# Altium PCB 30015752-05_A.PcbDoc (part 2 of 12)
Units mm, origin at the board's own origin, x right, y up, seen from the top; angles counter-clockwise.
Board outline 100.05 x 72 mm, 10 copper layers (Top, GND_2, Signal_3, Signal_4, PWR_5, GND_6, Signal_7, Signal_8, GND_9, Bottom), stack 1.493 mm thick; 577 components, 546 nets, 2389 pads, 1412 vias.
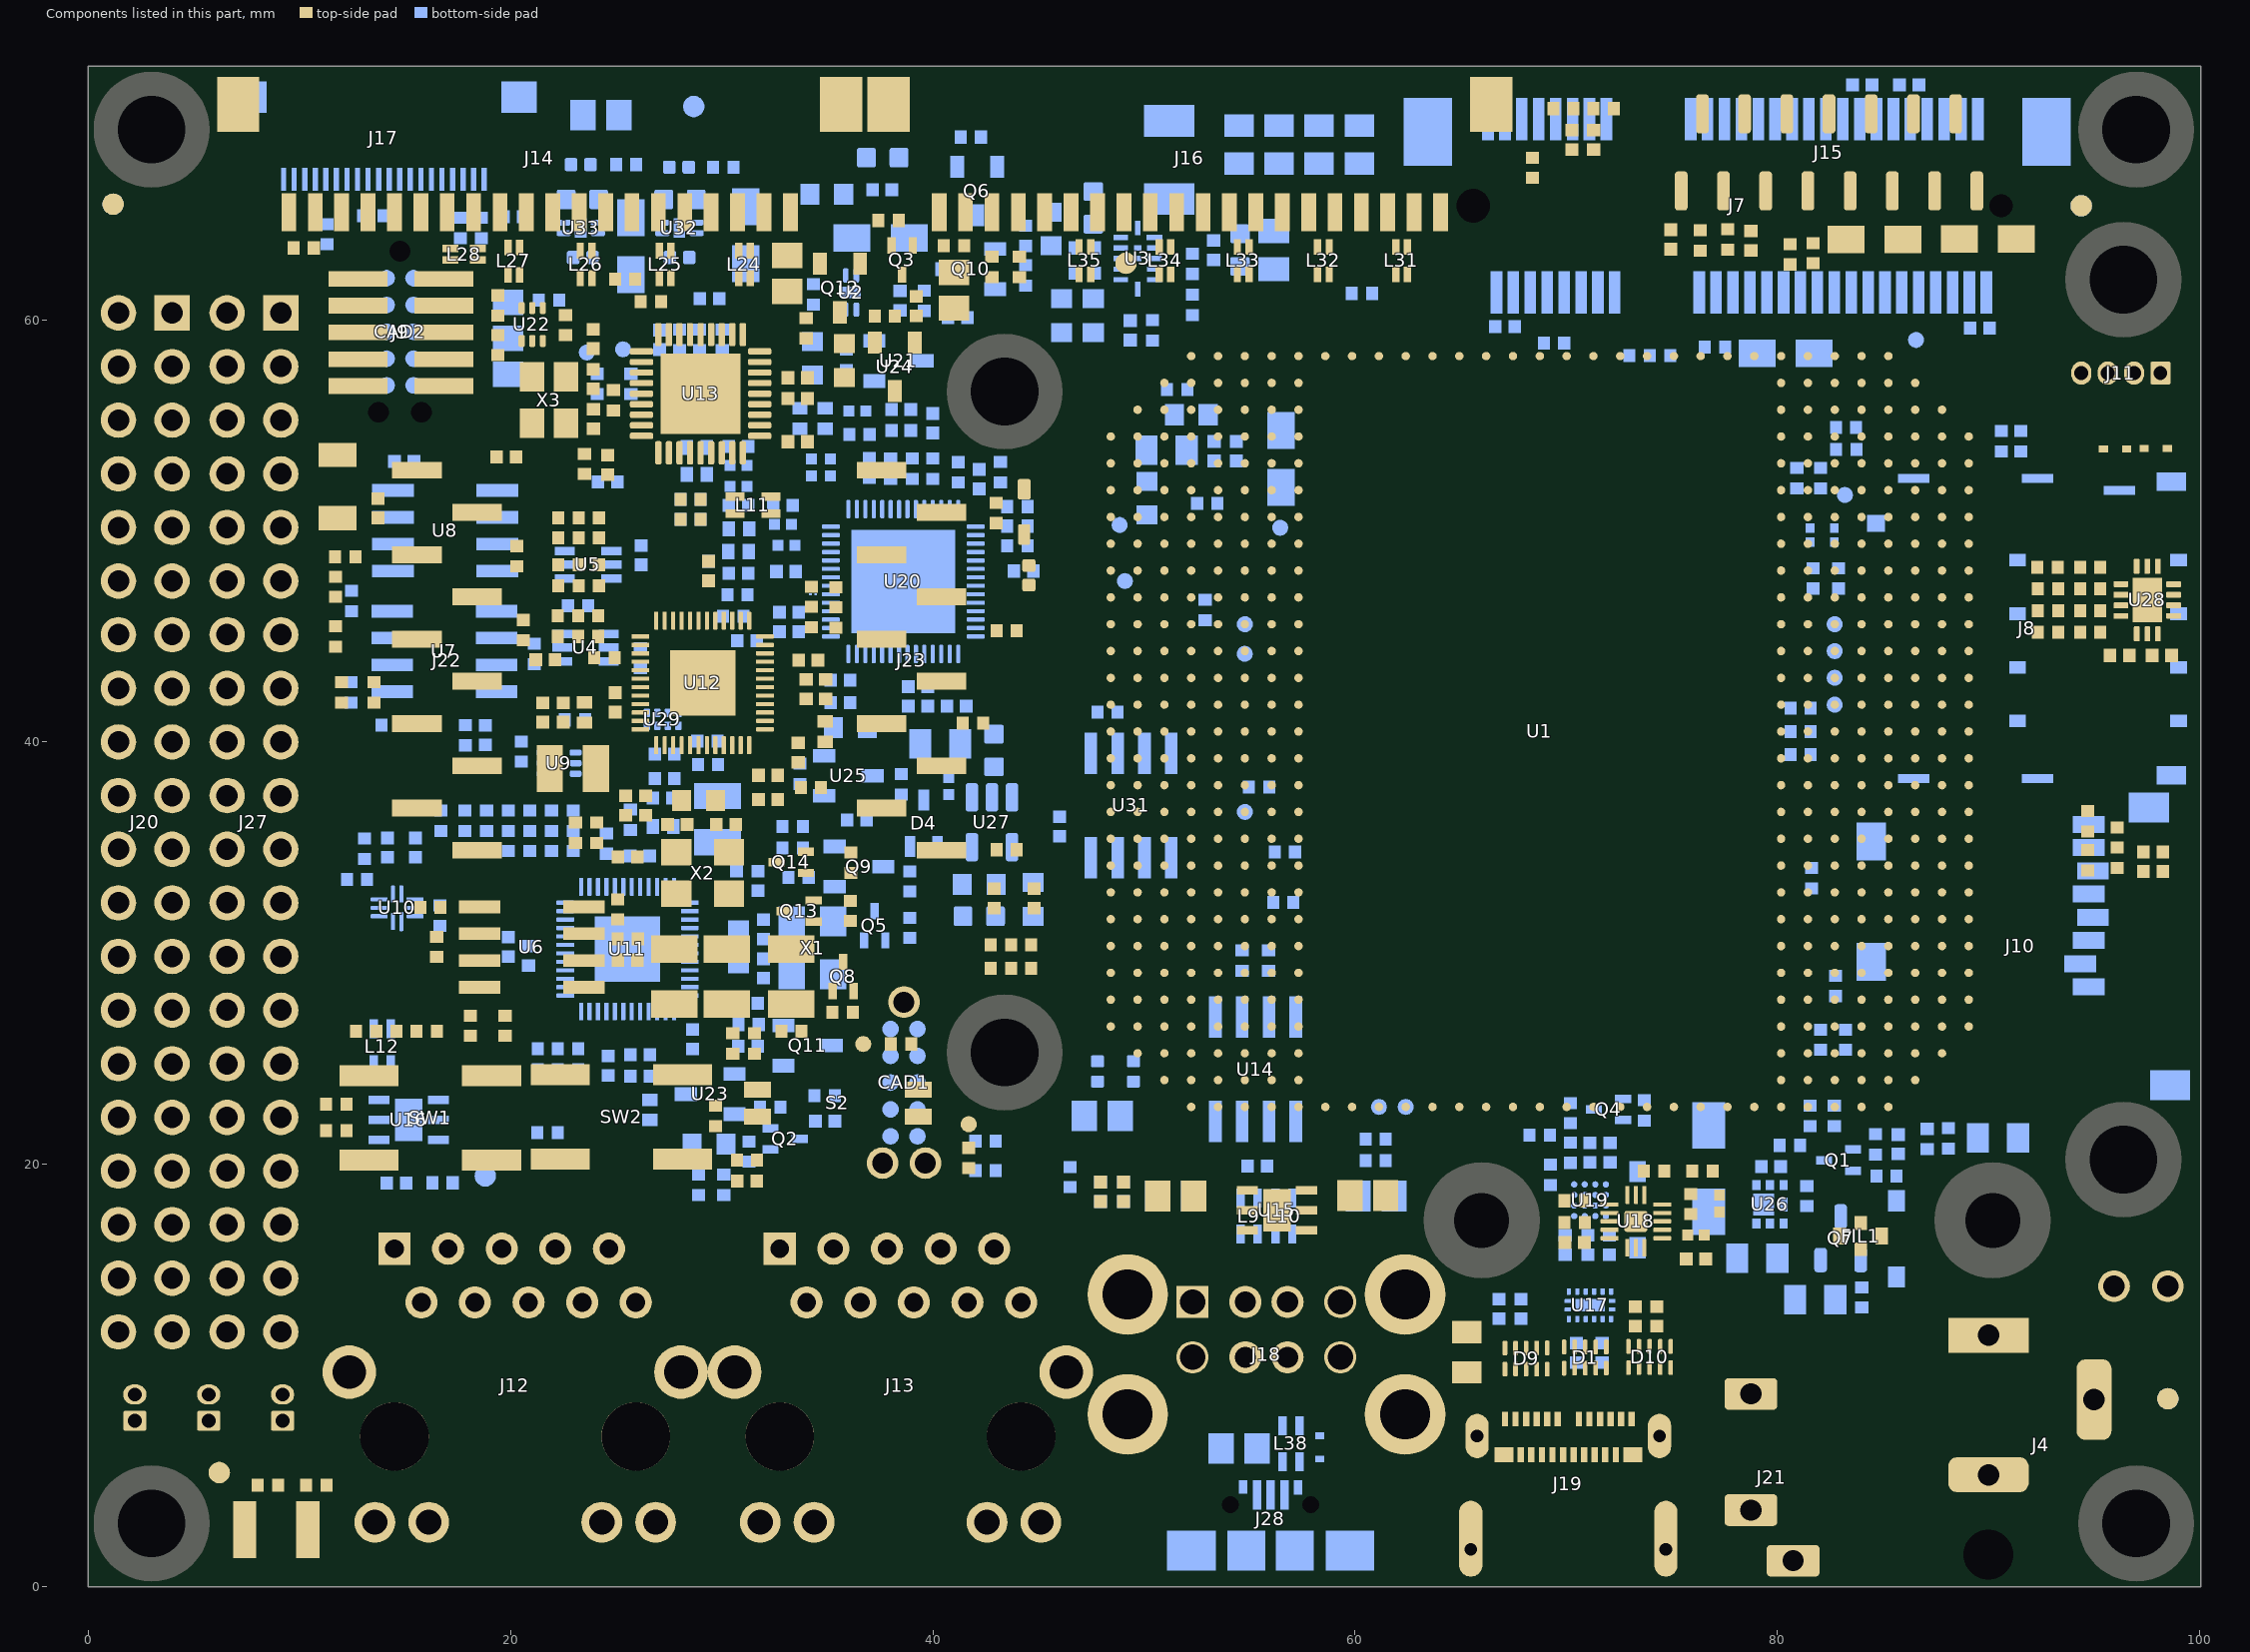
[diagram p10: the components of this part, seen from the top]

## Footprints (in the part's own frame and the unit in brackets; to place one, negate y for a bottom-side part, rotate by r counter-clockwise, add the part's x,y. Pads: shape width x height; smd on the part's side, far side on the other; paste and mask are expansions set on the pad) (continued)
CAPC0603X33N [mm]
  rect 0.46x0.42 smd: 1(-0.33,0) 2(0.33,0)
  body extent -0.3,-0.16 0.3,0.16, height 0.33
CAPC1005X55L [mm]
  rect 0.52x0.52 smd mask+0.05: 1(-0.4,0) 2(0.4,0)
  body extent -0.5,-0.25 0.5,0.25, height 0.55
CAPC1005X55N#1 [mm]
  rect 0.6x0.62 smd mask+0.05: 1(-0.46,0) 2(0.46,0)
  body extent -0.5,-0.25 0.5,0.25, height 0.55
CAPC1005X55N#2 [mm]
  rrect30% 0.6x0.62 smd mask+0.1: 1(-0.46,0) 2(0.46,0)
  body extent -0.5,-0.25 0.5,0.25, height 0.55
CAPC1608X90N [mm] "0603"
  rrect22% 0.89x0.93 smd: 1(-0.77,0) 2(0.77,0)
  body extent -0.8,-0.4 0.8,0.4, height 0.9
CAPC2013X135N [mm] "0805, 1.35mm max height"
  rect 1.05x1.4 smd: 1(-0.9,0) 2(0.9,0)
  body extent -1,-0.62 1,0.63, height 1.35
CAPC2013X145N [mm] "0805, 1.45mm max height"
  rect 1.15x1.45 smd: 1(-0.9,0) 2(0.9,0)
  body extent -1.05,-0.67 1.05,0.68, height 1.45
CAPC3216X190N [mm]
  rect 1.15x1.8 smd: 1(-1.5,0) 2(1.5,0)
  body extent -1.6,-0.8 1.6,0.8, height 1.9
CAPMP3216X120N [mm]
  rect 1.75x1.3 smd: 1(-1.35,0) 2(1.35,0)
  body extent -1.7,-0.9 1.7,0.9, height 1.21
CC8X_LGA [mm]
  round 0.4 smd mask+0.05: A4(-13.97,20.32) A5(-12.7,20.32) A6(-11.43,20.32) A7(-10.16,20.32) A8(-8.89,20.32) A9(-7.62,20.32) A10(-6.35,20.32) A11(-5.08,20.32) A12(-3.81,20.32) A13(-2.54,20.32) A14(-1.27,20.32) A15(0,20.32) A16(1.27,20.32) A17(2.54,20.32) A18(3.81,20.32) A19(5.08,20.32) A20(6.35,20.32) A21(7.62,20.32) A22(8.89,20.32) A23(10.16,20.32) A24(11.43,20.32) A25(12.7,20.32) A26(13.97,20.32) AA1(-17.78,-5.08) AA29(17.78,-5.08) AB1(-17.78,-6.35) AB29(17.78,-6.35) AC1(-17.78,-7.62) AC29(17.78,-7.62) AD1(-17.78,-8.89) AD29(17.78,-8.89) AE1(-17.78,-10.16) AE29(17.78,-10.16) AF1(-17.78,-11.43) AF2(-16.51,-11.43) AF3(-15.24,-11.43) AF4(-13.97,-11.43) AF5(-12.7,-11.43) AF6(-11.43,-11.43) AF7(-10.16,-11.43) AF8(-8.89,-11.43) AF9(-7.62,-11.43) AF10(-6.35,-11.43) AF11(-5.08,-11.43) AF12(-3.81,-11.43) AF13(-2.54,-11.43) AF14(-1.27,-11.43) AF15(0,-11.43) AF16(1.27,-11.43) AF17(2.54,-11.43) AF18(3.81,-11.43) AF19(5.08,-11.43) AF20(6.35,-11.43) AF21(7.62,-11.43) AF22(8.89,-11.43) AF23(10.16,-11.43) AF24(11.43,-11.43) AF25(12.7,-11.43) AF26(13.97,-11.43) AF27(15.24,-11.43) AF28(16.51,-11.43) AF29(17.78,-11.43) AG1(-17.78,-12.7) AG2(-16.51,-12.7) AG3(-15.24,-12.7) AG4(-13.97,-12.7) AG5(-12.7,-12.7) AG6(-11.43,-12.7) AG7(-10.16,-12.7) AG8(-8.89,-12.7) AG9(-7.62,-12.7) AG10(-6.35,-12.7) AG11(-5.08,-12.7) AG12(-3.81,-12.7) AG13(-2.54,-12.7) AG14(-1.27,-12.7) AG15(0,-12.7) AG16(1.27,-12.7) AG17(2.54,-12.7) AG18(3.81,-12.7) AG19(5.08,-12.7) AG20(6.35,-12.7) AG21(7.62,-12.7) AG22(8.89,-12.7) AG23(10.16,-12.7) AG24(11.43,-12.7) AG25(12.7,-12.7) AG26(13.97,-12.7) AG27(15.24,-12.7) AG28(16.51,-12.7) AG29(17.78,-12.7) AH1(-17.78,-13.97) AH2(-16.51,-13.97) AH3(-15.24,-13.97) AH4(-13.97,-13.97) AH5(-12.7,-13.97) AH6(-11.43,-13.97) AH7(-10.16,-13.97) AH8(-8.89,-13.97) AH9(-7.62,-13.97) AH10(-6.35,-13.97) AH11(-5.08,-13.97) AH12(-3.81,-13.97) AH13(-2.54,-13.97) AH14(-1.27,-13.97) AH15(0,-13.97) AH16(1.27,-13.97) AH17(2.54,-13.97) AH18(3.81,-13.97) AH19(5.08,-13.97) AH20(6.35,-13.97) AH21(7.62,-13.97) AH22(8.89,-13.97) AH23(10.16,-13.97) AH24(11.43,-13.97) AH25(12.7,-13.97) AH26(13.97,-13.97) AH27(15.24,-13.97) AH28(16.51,-13.97) AH29(17.78,-13.97) AJ1(-17.78,-15.24) AJ2(-16.51,-15.24) AJ3(-15.24,-15.24) AJ4(-13.97,-15.24) AJ5(-12.7,-15.24) AJ6(-11.43,-15.24) AJ7(-10.16,-15.24) AJ8(-8.89,-15.24) AJ9(-7.62,-15.24) AJ10(-6.35,-15.24) AJ11(-5.08,-15.24) AJ12(-3.81,-15.24) AJ13(-2.54,-15.24) AJ14(-1.27,-15.24) AJ15(0,-15.24) AJ16(1.27,-15.24) AJ17(2.54,-15.24) AJ18(3.81,-15.24) AJ19(5.08,-15.24) AJ20(6.35,-15.24) AJ21(7.62,-15.24) AJ22(8.89,-15.24) AJ23(10.16,-15.24) AJ24(11.43,-15.24) AJ25(12.7,-15.24) AJ26(13.97,-15.24) AJ27(15.24,-15.24) AJ28(16.51,-15.24) AJ29(17.78,-15.24) AK1(-17.78,-16.51) AK2(-16.51,-16.51) AK3(-15.24,-16.51) AK4(-13.97,-16.51) AK5(-12.7,-16.51) AK6(-11.43,-16.51) AK7(-10.16,-16.51) AK8(-8.89,-16.51) AK9(-7.62,-16.51) AK10(-6.35,-16.51) AK11(-5.08,-16.51) AK12(-3.81,-16.51) AK13(-2.54,-16.51) AK14(-1.27,-16.51) AK15(0,-16.51) AK16(1.27,-16.51) AK17(2.54,-16.51) AK18(3.81,-16.51) AK19(5.08,-16.51) AK20(6.35,-16.51) AK21(7.62,-16.51) AK22(8.89,-16.51) AK23(10.16,-16.51) AK24(11.43,-16.51) AK25(12.7,-16.51) AK26(13.97,-16.51) AK27(15.24,-16.51) AK28(16.51,-16.51) AK29(17.78,-16.51) AL2(-16.51,-17.78) AL3(-15.24,-17.78) AL4(-13.97,-17.78) AL5(-12.7,-17.78) AL6(-11.43,-17.78) AL7(-10.16,-17.78) AL8(-8.89,-17.78) AL9(-7.62,-17.78) AL10(-6.35,-17.78) AL11(-5.08,-17.78) AL12(-3.81,-17.78) AL13(-2.54,-17.78) AL14(-1.27,-17.78) AL15(0,-17.78) AL16(1.27,-17.78) AL17(2.54,-17.78) AL18(3.81,-17.78) AL19(5.08,-17.78) AL20(6.35,-17.78) AL21(7.62,-17.78) AL22(8.89,-17.78) AL23(10.16,-17.78) AL24(11.43,-17.78) AL25(12.7,-17.78) AL26(13.97,-17.78) AL27(15.24,-17.78) AL28(16.51,-17.78) AM3(-15.24,-19.05) AM4(-13.97,-19.05) AM5(-12.7,-19.05) AM6(-11.43,-19.05) AM7(-10.16,-19.05) AM8(-8.89,-19.05) AM9(-7.62,-19.05) AM10(-6.35,-19.05) AM11(-5.08,-19.05) AM12(-3.81,-19.05) AM13(-2.54,-19.05) AM14(-1.27,-19.05) AM15(0,-19.05) AM16(1.27,-19.05) AM17(2.54,-19.05) AM18(3.81,-19.05) AM19(5.08,-19.05) AM20(6.35,-19.05) AM21(7.62,-19.05) AM22(8.89,-19.05) AM23(10.16,-19.05) AM24(11.43,-19.05) AM25(12.7,-19.05) AM26(13.97,-19.05) AM27(15.24,-19.05) AN4(-13.97,-20.32) AN5(-12.7,-20.32) AN6(-11.43,-20.32) AN7(-10.16,-20.32) AN8(-8.89,-20.32) AN9(-7.62,-20.32) AN10(-6.35,-20.32) AN11(-5.08,-20.32) AN12(-3.81,-20.32) AN13(-2.54,-20.32) AN14(-1.27,-20.32) AN15(0,-20.32) AN16(1.27,-20.32) AN17(2.54,-20.32) AN18(3.81,-20.32) AN19(5.08,-20.32) AN20(6.35,-20.32) AN21(7.62,-20.32) AN22(8.89,-20.32) AN23(10.16,-20.32) AN24(11.43,-20.32) AN25(12.7,-20.32) AN26(13.97,-20.32) B3(-15.24,19.05) B4(-13.97,19.05) B5(-12.7,19.05) B6(-11.43,19.05) B7(-10.16,19.05) B8(-8.89,19.05) B9(-7.62,19.05) B10(-6.35,19.05) B11(-5.08,19.05) B12(-3.81,19.05) B13(-2.54,19.05) B14(-1.27,19.05) B15(0,19.05) B16(1.27,19.05) B17(2.54,19.05) B18(3.81,19.05) B19(5.08,19.05) B20(6.35,19.05) B21(7.62,19.05) B22(8.89,19.05) B23(10.16,19.05) B24(11.43,19.05) B25(12.7,19.05) B26(13.97,19.05) B27(15.24,19.05) C2(-16.51,17.78) C3(-15.24,17.78) C4(-13.97,17.78) C5(-12.7,17.78) C6(-11.43,17.78) C7(-10.16,17.78) C8(-8.89,17.78) C9(-7.62,17.78) C10(-6.35,17.78) C11(-5.08,17.78) C12(-3.81,17.78) C13(-2.54,17.78) C14(-1.27,17.78) C15(0,17.78) C16(1.27,17.78) C17(2.54,17.78) C18(3.81,17.78) C19(5.08,17.78) C20(6.35,17.78) C21(7.62,17.78) C22(8.89,17.78) C23(10.16,17.78) C24(11.43,17.78) C25(12.7,17.78) C26(13.97,17.78) C27(15.24,17.78) C28(16.51,17.78) D1(-17.78,16.51) D2(-16.51,16.51) D3(-15.24,16.51) D4(-13.97,16.51) D5(-12.7,16.51) D6(-11.43,16.51) D7(-10.16,16.51) D8(-8.89,16.51) D9(-7.62,16.51) D10(-6.35,16.51) D11(-5.08,16.51) D12(-3.81,16.51) D13(-2.54,16.51) D14(-1.27,16.51) D15(0,16.51) D16(1.27,16.51) D17(2.54,16.51) D18(3.81,16.51) D19(5.08,16.51) D20(6.35,16.51) D21(7.62,16.51) D22(8.89,16.51) D23(10.16,16.51) D24(11.43,16.51) D25(12.7,16.51) D26(13.97,16.51) D27(15.24,16.51) D28(16.51,16.51) D29(17.78,16.51) E1(-17.78,15.24) E2(-16.51,15.24) E3(-15.24,15.24) E4(-13.97,15.24) E5(-12.7,15.24) E6(-11.43,15.24) E7(-10.16,15.24) E8(-8.89,15.24) E9(-7.62,15.24) E10(-6.35,15.24) E11(-5.08,15.24) E12(-3.81,15.24) E13(-2.54,15.24) E14(-1.27,15.24) E15(0,15.24) E16(1.27,15.24) E17(2.54,15.24) E18(3.81,15.24) E19(5.08,15.24) E20(6.35,15.24) E21(7.62,15.24) E22(8.89,15.24) E23(10.16,15.24) E24(11.43,15.24) E25(12.7,15.24) E26(13.97,15.24) E27(15.24,15.24) E28(16.51,15.24) E29(17.78,15.24) F1(-17.78,13.97) F2(-16.51,13.97) F3(-15.24,13.97) F4(-13.97,13.97) F5(-12.7,13.97) F6(-11.43,13.97) F7(-10.16,13.97) F8(-8.89,13.97) F9(-7.62,13.97) F10(-6.35,13.97) F11(-5.08,13.97) F12(-3.81,13.97) F13(-2.54,13.97) F14(-1.27,13.97) F15(0,13.97) F16(1.27,13.97) F17(2.54,13.97) F18(3.81,13.97) F19(5.08,13.97) F20(6.35,13.97) F21(7.62,13.97) F22(8.89,13.97) F23(10.16,13.97) F24(11.43,13.97) F25(12.7,13.97) F26(13.97,13.97) F27(15.24,13.97) F28(16.51,13.97) F29(17.78,13.97) G1(-17.78,12.7) G2(-16.51,12.7) G3(-15.24,12.7) G4(-13.97,12.7) G5(-12.7,12.7) G6(-11.43,12.7) G7(-10.16,12.7) G8(-8.89,12.7) G9(-7.62,12.7) G10(-6.35,12.7) G11(-5.08,12.7) G12(-3.81,12.7) G13(-2.54,12.7) G14(-1.27,12.7) G15(0,12.7) G16(1.27,12.7) G17(2.54,12.7) G18(3.81,12.7) G19(5.08,12.7) G20(6.35,12.7) G21(7.62,12.7) G22(8.89,12.7) G23(10.16,12.7) G24(11.43,12.7) G25(12.7,12.7) G26(13.97,12.7) G27(15.24,12.7) G28(16.51,12.7) G29(17.78,12.7) H1(-17.78,11.43) H2(-16.51,11.43) H3(-15.24,11.43) H4(-13.97,11.43) H5(-12.7,11.43) H6(-11.43,11.43) H7(-10.16,11.43) H8(-8.89,11.43) H9(-7.62,11.43) H10(-6.35,11.43) H11(-5.08,11.43) H12(-3.81,11.43) H13(-2.54,11.43) H14(-1.27,11.43) H15(0,11.43) H16(1.27,11.43) H17(2.54,11.43) H18(3.81,11.43) H19(5.08,11.43) H20(6.35,11.43) H21(7.62,11.43) H22(8.89,11.43) H23(10.16,11.43) H24(11.43,11.43) H25(12.7,11.43) H26(13.97,11.43) H27(15.24,11.43) H28(16.51,11.43) H29(17.78,11.43) J1(-17.78,10.16) J29(17.78,10.16) K1(-17.78,8.89) K29(17.78,8.89) L1(-17.78,7.62) L29(17.78,7.62) M1(-17.78,6.35) M29(17.78,6.35) N1(-17.78,5.08) N29(17.78,5.08) P1(-17.78,3.81) P29(17.78,3.81) R1(-17.78,2.54) R29(17.78,2.54) T1(-17.78,1.27) T29(17.78,1.27) U1(-17.78,0) U29(17.78,0) V1(-17.78,-1.27) V29(17.78,-1.27) W1(-17.78,-2.54) W29(17.78,-2.54) Y1(-17.78,-3.81) Y29(17.78,-3.81)
  Keep-Out Layer board cut-out: 16.78,9.93 16.78,10.029 16.704,10.213 16.563,10.354 16.379,10.43 16.28,10.43 16.28,10.43 -16.28,10.43 -16.379,10.43 -16.563,10.354 -16.704,10.213 -16.78,10.029 -16.78,9.93 -16.78,9.93 -16.78,-9.93 -16.78,-10.029 -16.704,-10.213 -16.563,-10.354 -16.379,-10.43 -16.28,-10.43 -16.28,-10.43 16.28,-10.43 16.379,-10.43 16.563,-10.354 16.704,-10.213 16.78,-10.029 16.78,-9.93 16.78,-9.93
  body extent -20,-22.5 20,22.5, height 5.35
conn_CSCD443CCS011B00G [mil] "Bobbintron : CSCD443CCS011B00G"
  rect 65x150 hole 40 slot 126 at 90 deg: 1(0,0)
  rrect50% 65x150 / inner rect 65x150 / far side rrect50% 65x150 hole 40 slot 126 at 90 deg: 2(-260,0)
  rrect50% 150x65 / inner rect 150x65 / far side rrect50% 150x65 hole 40 slot 126 at 0 deg: 3(-120,-197.01)
  round 0 hole 93 unplated: 4(-409,0)
  body extent -571,-207 20,177, height 433
CUI_SJ1-3533N [mm] "CON PWR JCK STEREO 3.5MM R/A 3.05mm"
  rrect25% 1.5x2.5 hole 1 slot 2 at 90 deg: 1(0,0) 2(2.4,2) 3(7.9,2)
  body extent -5.2,-4 12.8,4.2, height 12.3
DIOM5127X229AN [mm]
  rect 2.2x1.55 smd: A(2.05,0) K(-2.05,0)
  silkscreen extent -3.45,1.33 -3.15,1.63, body extent -2.64,-1.4 2.64,1.4, height 2.34
FAIRCHILD_MICROFET_2X2 [mm]
  rect 0.47x0.4 smd mask+0.05: 1(-0.91,0.65) 2(-0.91,0) 3(-0.91,-0.65) 4(0.91,-0.65) 5(0.91,0) 6(0.91,0.65)
  rect 1.05x1 smd mask+0: 7(0,0.3)
  rect 0.66x0.4 smd mask+0.05: 8(0,-0.65)
  body extent -1,-1 1,1, height 0.85
FCI_SFW15S-2STE1LF [mm] "CONN FFC FPC VERT 15POS 1MM SMD"
  rrect50% 0.6x1.85 smd: 1(-7,-1.825) 2(-6,1.825) 3(-5,-1.825) 4(-4,1.825) 5(-3,-1.825) 6(-2,1.825) 7(-1,-1.825) 8(0,1.825) 9(1,-1.825) 10(2,1.825) 11(3,-1.825) 12(4,1.825) 13(5,-1.825) 14(6,1.825) 15(7,-1.825)
  body extent -10.7,-2.25 10.7,2.25, height 5.31
fiducial_40mil_round [mil]
  round 40 smd paste-40 mask+20: 1(0,0)
  Top pour cut-out: -40,0 -36.96,15.31 -28.28,28.28 -15.31,36.96 0,40 0,40 15.31,36.96 28.28,28.28 36.96,15.31 40,0 40,0 36.96,-15.31 28.28,-28.28 15.31,-36.96 0,-40 0,-40 -15.31,-36.96 -28.28,-28.28 -36.96,-15.31 -40,0
FIL_DLP11S [mm]
  rect 0.75x0.35 smd: 1(-0.65,-0.275) 2(0.65,-0.275) 3(0.65,0.275) 4(-0.65,0.275)
  body extent -0.67,-0.55 0.68,0.55, height 0.92
FIL_DLW21H [mm]
  rect 0.9x0.4 smd: 1(-0.85,-0.4) 2(0.85,-0.4) 3(0.85,0.4) 4(-0.85,0.4)
  body extent -1.1,-0.7 1.1,0.7, height 1
FIL_NFM21P [mm]
  rect 0.6x0.8 smd: 1(-1,0) 3(1,0)
  rect 0.6x0.65 smd: 2(0,0.625) 2(0,-0.625)
  silkscreen extent -2.05,-0.8 1.15,0.8, body extent -1,-0.62 1,0.63, height 0.85
FOXCONN_AS0B221-S68Q-7H [mm]
  rect 0.55x2 smd: 1(0.7,-4.1) 2(1.1,4.1) 3(1.5,-4.1) 4(1.9,4.1) 5(2.3,-4.1) 6(2.7,4.1) 7(3.1,-4.1) 8(3.5,4.1) 9(3.9,-4.1) 10(4.3,4.1) 11(4.7,-4.1) 12(5.1,4.1) 13(5.5,-4.1) 14(5.9,4.1) 15(6.3,-4.1) 16(6.7,4.1) 17(10.3,-4.1) 18(10.7,4.1) 19(11.1,-4.1) 20(11.5,4.1) 21(11.9,-4.1) 22(12.3,4.1) 23(12.7,-4.1) 24(13.1,4.1) 25(13.5,-4.1) 26(13.9,4.1) 27(14.3,-4.1) 28(14.7,4.1) 29(15.1,-4.1) 30(15.5,4.1) 31(15.9,-4.1) 32(16.3,4.1) 33(16.7,-4.1) 34(17.1,4.1) 35(17.5,-4.1) 36(17.9,4.1) 37(18.3,-4.1) 38(18.7,4.1) 39(19.1,-4.1) 40(19.5,4.1) 41(19.9,-4.1) 42(20.3,4.1) 43(20.7,-4.1) 44(21.1,4.1) 45(21.5,-4.1) 46(21.9,4.1) 47(22.3,-4.1) 48(22.7,4.1) 49(23.1,-4.1) 50(23.5,4.1) 51(23.9,-4.1) 52(24.3,4.1)
  round 0 hole 1.6 unplated: H1(0,0)
  round 0 hole 1.1 unplated: H2(25,0)
  rect 2.3x3.2 smd: MT1(-2.15,-3.5) MT2(27.15,-3.5)
  body extent -2.4,-4.75 27.4,4.75, height 6.8
HIROSE_DF14A-20P-1.25H [mm]
  rect 0.7x1.8 smd: 1(11.875,-2.55) 2(10.625,-2.55) 3(9.375,-2.55) 4(8.125,-2.55) 5(6.875,-2.55) 6(5.625,-2.55) 7(4.375,-2.55) 8(3.125,-2.55) 9(1.875,-2.55) 10(0.625,-2.55) 11(-0.625,-2.55) 12(-1.875,-2.55) 13(-3.125,-2.55) 14(-4.375,-2.55) 15(-5.625,-2.55) 16(-6.875,-2.55) 17(-8.125,-2.55) 18(-9.375,-2.55) 19(-10.625,-2.55) 20(-11.875,-2.55)
  rect 2x2.6 smd: MT1(14.275,2.55) MT21(-14.275,2.55)
  body extent -14.97,-3.02 14.98,3.68, height 2.49
INDC1005X60N [mm]
  rect 0.59x0.72 smd: 1(-0.48,0) 2(0.48,0)
  body extent -0.5,-0.25 0.5,0.25, height 0.6
INDC2013X110N [mm]
  rect 1.2x1.45 smd: 1(-0.85,0) 2(0.85,0)
  body extent -1.1,-0.72 1.1,0.72, height 1.1
INDC2520X100L60N [mm] "Inductor, Chip; 2.50 mm L X 2.00 mm W X 1.00 mm H body"
  rect 1.24x2.22 smd: 1(-1.09,0) 2(1.09,0)
  body extent -1.25,-1 1.25,1, height 1
INDM_SRP4020TA [mm]
  rect 1.5x2.4 smd: 1(-1.85,0) 2(1.85,0)
  body extent -2.2,-2.1 2.2,2.1, height 1.91
KYCON_KMMX-ABSMT5 [mm]
  rect 0.4x0.7 smd mask+0.058: 1(-1.3,3)
  rect 0.4x1.4 smd: 2(-0.65,2.65) 3(0,2.65) 4(0.65,2.65)
  rect 0.4x0.65 smd mask+0.058: 5(1.3,3.025)
  rect 2.3x1.9 smd: 6(-3.75,0) 9(3.75,0)
  rect 1.8x1.9 smd: 7(-1.15,0) 8(1.15,0)
  round 0 hole 0.813 unplated: 10(-1.9,2.18) 11(1.9,2.18)
  Top region: -1.1,2.7 -1.1,1.95 -1.275,1.95 -1.275,2.18 -1.278,2.235 -1.28,2.258 -1.282,2.278 -1.285,2.29 -1.288,2.305 -1.29,2.315 -1.292,2.328 -1.3,2.355 -1.308,2.378 -1.315,2.4 -1.32,2.412 -1.335,2.448 -1.34,2.458 -1.342,2.462 -1.345,2.468 -1.358,2.49 -1.372,2.515 -1.388,2.538 -1.4,2.555 -1.418,2.578 -1.435,2.598 -1.482,2.645 -1.5,2.66 -1.5,2.7
  Top region: 1.1,2.7 1.1,1.95 1.275,1.95 1.275,2.18 1.278,2.235 1.28,2.258 1.282,2.278 1.285,2.29 1.288,2.305 1.29,2.315 1.292,2.328 1.3,2.355 1.308,2.378 1.315,2.4 1.32,2.412 1.335,2.448 1.34,2.458 1.342,2.462 1.345,2.468 1.358,2.49 1.372,2.515 1.388,2.538 1.4,2.555 1.418,2.578 1.435,2.598 1.482,2.645 1.5,2.66 1.5,2.7
  body extent -4.4,-2.72 4.4,2.88, height 2.78
KYCON_KUSBX-AS2N_Flex [mm]
  rect 1.524x1.524 hole 1.2: A1(0,0)
  round 1.524 hole 1: A2(2.5,0) A3(4.5,0) B2(2.5,-2.62) B3(4.5,-2.62)
  round 1.524 hole 1.2: A4(7,0) B1(0,-2.62) B4(7,-2.62)
  round 3.81 hole 2.362: SH1(-3.07,-5.33) SH2(-3.07,0.35) SH3(10.07,-5.33) SH4(10.07,0.35)
  silkscreen extent -0.18,1.97 0.18,2.33, body extent -4.33,-16.08 11.33,1.42, height 16.1
LEDM3020X130N [mm]
  rect 1.3x2.2 smd: A(-1.3,0) K(1.3,0)
  body extent -1.6,-1.1 1.6,1.1, height 1.5
MH_185_125_NP [mm]
  round 3.175 hole 3.175 unplated: 1(0,0)
  Keep-Out Layer circle w0.102: c0,0 r2.349
"MILLMAX_ 802-10-040-62-001000" [mil]
  rect 66x66 hole 40 mask+3.94: 1(100,0)
  round 66 hole 40 mask+3.94: 2(0,0) 3(100,-100) 4(0,-100) 5(100,-200) 6(0,-200) 7(100,-300) 8(0,-300) 9(100,-400) 10(0,-400) 11(100,-500) 12(0,-500) 13(100,-600) 14(0,-600) 15(100,-700) 16(0,-700) 17(100,-800) 18(0,-800) 19(100,-900) 20(0,-900) 21(100,-1000) 22(0,-1000) 23(100,-1100) 24(0,-1100) 25(100,-1200) 26(0,-1200) 27(100,-1300) 28(0,-1300) 29(100,-1400) 30(0,-1400) 31(100,-1500) 32(0,-1500) 33(100,-1600) 34(0,-1600) 35(100,-1700) 36(0,-1700) 37(100,-1800) 38(0,-1800) 39(100,-1900) 40(0,-1900)
  body extent -50,-1950 150,50, height 301
MOLEX_53047-0210 [mm]
  rrect20% 0.95x1.1 hole 0.65: 1(0,0)
  oval 0.95x1.1 hole 0.65: 2(1.25,0)
  body extent -1.52,-1.15 2.73,2.05, height 4.2
MOLEX_53047-0410 [mm]
  rrect20% 0.95x1.1 hole 0.65: 1(0,0)
  oval 0.95x1.1 hole 0.65: 2(1.25,0) 3(2.5,0) 4(3.75,0)
  body extent -1.52,-1.15 5.23,2.05, height 4.2
MOLEX_78727-0001 [mm]
  rect 0.8x0.6 smd: 1(0.33,4.38) 2(0.33,1.84) 3(0.33,-0.7) 4(0.33,-3.24) 5(-7.29,4.38) 6(-7.29,1.84) 7(-7.29,-0.7) 8(-7.29,-3.24)
  rect 0.85x0.8 smd: 9(-13.99,-4.98)
  rect 1.5x0.42 smd: 10(-2.47,-6.54) 12(-6.35,7.11) 13(-12.21,7.11) 14(-12.21,-7.11) 15(-6.35,-7.11)
  rect 1.4x0.87 smd: 11(0,6.95) 16(0,-6.95)
  body extent -14.53,-7.26 0.69,7.27, height 1.4
MOLEX_201267-0005 [mm]
  rect 0.3x0.7 smd mask+0.05: A1(-3,3.965) A2(-2.5,3.965) A3(-2,3.965) A4(-1.5,3.965) A5(-1,3.965) A6(-0.5,3.965) A7(0.5,3.965) A8(1,3.965) A9(1.5,3.965) A10(2,3.965) A11(2.5,3.965) A12(3,3.965) B2(2.25,2.265) B3(1.75,2.265) B4(1.25,2.265) B5(0.75,2.265) B6(0.25,2.265) B7(-0.25,2.265) B8(-0.75,2.265) B9(-1.25,2.265) B10(-1.75,2.265) B11(-2.25,2.265)
  rect 0.9x0.7 smd mask+0.05: B1(3.05,2.265) B12(-3.05,2.265)
  oval 1.1x2.1 hole 0.6 slot 1.6 at 90 deg mask+0.05: MT1(-4.32,3.155) MT2(4.32,3.155)
  oval 1.1x3.6 hole 0.6 slot 2.1 at 90 deg copper offset 0,0.5 mask+0.05: MT3(-4.62,-2.205) MT4(4.62,-2.205)
  body extent -4.69,-4.15 4.69,4.15, height 3.7
MOLEX_500873-0806 [mm]
  rect 0.8x1.5 smd: 1(0,0) 2(1.1,-0.4) 3(2.2,0) 4(3.3,0.2) 5(4.4,0) 6(5.5,0.2) 7(6.6,0) 8(7.7,0)
  rect 1.8x1.4 smd: 9(1.2,-10.3) 10(6.9,-10.3)
  rect 1.4x1.9 smd: 11(8.5,2.85) 12(-4.65,3.85)
  body extent -5.05,-10.7 8.95,4.5, height 1.87
NET_TIE_4mil [mil] "Net Tie for 4mil traces"
  rect 5x4 smd paste-5 mask-5: 1(-5,0) 2(5,0)
  Top region: -2.99,2 3.01,2 3.01,-2 -2.99,-2
omron_xf2m-2015-1a [mm]
  rect 0.25x1.1 smd: 1(-4.75,1.95) 2(-4.25,1.95) 3(-3.75,1.95) 4(-3.25,1.95) 5(-2.75,1.95) 6(-2.25,1.95) 7(-1.75,1.95) 8(-1.25,1.95) 9(-0.75,1.95) 10(-0.25,1.95) 11(0.25,1.95) 12(0.75,1.95) 13(1.25,1.95) 14(1.75,1.95) 15(2.25,1.95) 16(2.75,1.95) 17(3.25,1.95) 18(3.75,1.95) 19(4.25,1.95) 20(4.75,1.95)
  rect 1.7x1.5 smd: M1(6.4,-1.95) M2(-6.4,-1.95)
  body extent -7.05,-2.9 7.05,3.3, height 2.18
OSC210P320X250X90-4N [mm]
  rect 1.25x1.425 smd: 1(-0.975,1.25) 2(-0.975,-1.25) 3(0.975,-1.25) 4(0.975,1.25)
  body extent -1.3,-1.63 1.3,1.62, height 0.6
PQFN40P160X240X55-17T140X60N [mm] "Pullback Quad Flat No-Lead (PQFN with Tab), 0.40 mm pitch; rect., pin 1 on short dimension, 2 pin X 6 pin, 1.60 mm L X 2.40 mm W X 0.55 mm H body"
  rrect25% 0.3x0.2 smd mask+0.05: 1(-0.65,1) 2(-0.65,0.6) 3(-0.65,0.2) 4(-0.65,-0.2) 5(-0.65,-0.6) 6(-0.65,-1) 9(0.65,-1) 10(0.65,-0.6) 11(0.65,-0.2) 12(0.65,0.2) 13(0.65,0.6) 14(0.65,1)
  rrect25% 0.2x0.3 smd mask+0.05: 7(-0.2,-1.05) 8(0.2,-1.05) 15(0.2,1.05) 16(-0.2,1.05)
  rect 0.6x1.4 smd paste-1.4 mask+0: 17(0,0)
  body extent -0.8,-1.2 0.8,1.2, height 0.55
PSON50P195X100X50-8N [mm] "Pullback Small Outline No-Lead (PSON), 0.50 mm pitch; 8 pin, 1.95 mm L X 1.00 mm W X 0.50 mm H body"
  rrect25% 0.4x0.3 smd mask+0.05: 1(-0.3,0.75) 2(-0.3,0.25) 3(-0.3,-0.25) 4(-0.3,-0.75) 5(0.3,-0.75) 6(0.3,-0.25) 7(0.3,0.25) 8(0.3,0.75)
  body extent -0.5,-0.98 0.5,0.97, height 0.5
QFN40P180X140X55-10N [mm] "Quad Flat No-Lead (QFN), 0.40 mm pitch; rect., 2 pin X 3 pin, 1.80 mm L X 1.40 mm W X 0.55 mm H body"
  rrect50% 0.91x0.2 smd mask+0.05: 1(-0.65,0.2)
  rrect50% 0.81x0.2 smd mask+0.05: 2(-0.65,-0.2) 6(0.65,-0.2) 7(0.65,0.2)
  rrect50% 0.2x0.81 smd mask+0.05: 3(-0.4,-0.85) 4(0,-0.85) 5(0.4,-0.85) 8(0.4,0.85) 9(0,0.85) 10(-0.4,0.85)
  silkscreen extent -1.35,0.5 -1.15,0.7, body extent -0.75,-0.95 0.75,0.95, height 0.55
QFN40P260X260X40-17T100X110N [mm] "Quad Flat No-Lead (QFN with Tab), 0.40 mm pitch; square, 5 pin X 3 pin, 2.60 mm L X 2.60 mm W X 0.40 mm H body"
  rrect25% 0.84x0.2 smd mask+0.05: 1(-1.25,0.8) 2(-1.25,0.4) 3(-1.25,0) 4(-1.25,-0.4) 5(-1.25,-0.8) 9(1.25,-0.8) 10(1.25,-0.4) 11(1.25,0) 12(1.25,0.4) 13(1.25,0.8)
  rrect25% 0.2x0.84 smd mask+0.05: 6(-0.4,-1.25) 7(0,-1.25) 8(0.4,-1.25) 14(0.4,1.25) 15(0,1.25) 16(-0.4,1.25)
  rrect25% 1.1x1 smd paste-0.153 mask+0.05: 17(0,0)
  body extent -1.35,-1.35 1.35,1.35, height 0.4
QFN40P600X600X80-49T380N [mm] "Quad Flat No-Lead (QFN with Tab), 0.40 mm pitch; square, 12 pin X 12 pin, 6.00 mm L X 6.00 mm W X 0.80 mm H body"
  rrect25% 0.84x0.2 smd mask+0.05: 1(-2.95,2.2) 2(-2.95,1.8) 3(-2.95,1.4) 4(-2.95,1) 5(-2.95,0.6) 6(-2.95,0.2) 7(-2.95,-0.2) 8(-2.95,-0.6) 9(-2.95,-1) 10(-2.95,-1.4) 11(-2.95,-1.8) 12(-2.95,-2.2) 25(2.95,-2.2) 26(2.95,-1.8) 27(2.95,-1.4) 28(2.95,-1) 29(2.95,-0.6) 30(2.95,-0.2) 31(2.95,0.2) 32(2.95,0.6) 33(2.95,1) 34(2.95,1.4) 35(2.95,1.8) 36(2.95,2.2)
  rrect25% 0.2x0.84 smd mask+0.05: 13(-2.2,-2.95) 14(-1.8,-2.95) 15(-1.4,-2.95) 16(-1,-2.95) 17(-0.6,-2.95) 18(-0.2,-2.95) 19(0.2,-2.95) 20(0.6,-2.95) 21(1,-2.95) 22(1.4,-2.95) 23(1.8,-2.95) 24(2.2,-2.95) 37(2.2,2.95) 38(1.8,2.95) 39(1.4,2.95) 40(1,2.95) 41(0.6,2.95) 42(0.2,2.95) 43(-0.2,2.95) 44(-0.6,2.95) 45(-1,2.95) 46(-1.4,2.95) 47(-1.8,2.95) 48(-2.2,2.95)
  rect 3.1x3.1 smd paste-3.1 mask+0: 49(0,0)
  Top region: -1.9,-1.9 -1.9,1.55 -1.55,1.9 1.9,1.9 1.9,-1.9 -1.9,-1.9
  body extent -3.05,-3.05 3.05,3.05, height 0.8
QFN40P700X700X80-57T560X560N [mm] "Quad Flat No-Lead (QFN with Tab), 0.40 mm pitch; square, 14 pin X 14 pin, 7.00 mm L X 7.00 mm W X 0.80 mm H body"
  rrect50% 0.86x0.2 smd mask+0.05: 1(-3.43,2.6) 2(-3.43,2.2) 3(-3.43,1.8) 4(-3.43,1.4) 5(-3.43,1) 6(-3.43,0.6) 7(-3.43,0.2) 8(-3.43,-0.2) 9(-3.43,-0.6) 10(-3.43,-1) 11(-3.43,-1.4) 12(-3.43,-1.8) 13(-3.43,-2.2) 14(-3.43,-2.6) 29(3.43,-2.6) 30(3.43,-2.2) 31(3.43,-1.8) 32(3.43,-1.4) 33(3.43,-1) 34(3.43,-0.6) 35(3.43,-0.2) 36(3.43,0.2) 37(3.43,0.6) 38(3.43,1) 39(3.43,1.4) 40(3.43,1.8) 41(3.43,2.2) 42(3.43,2.6)
  rrect50% 0.2x0.86 smd mask+0.05: 15(-2.6,-3.43) 16(-2.2,-3.43) 17(-1.8,-3.43) 18(-1.4,-3.43) 19(-1,-3.43) 20(-0.6,-3.43) 21(-0.2,-3.43) 22(0.2,-3.43) 23(0.6,-3.43) 24(1,-3.43) 25(1.4,-3.43) 26(1.8,-3.43) 27(2.2,-3.43) 28(2.6,-3.43) 43(2.6,3.43) 44(2.2,3.43) 45(1.8,3.43) 46(1.4,3.43) 47(1,3.43) 48(0.6,3.43) 49(0.2,3.43) 50(-0.2,3.43) 51(-0.6,3.43) 52(-1,3.43) 53(-1.4,3.43) 54(-1.8,3.43) 55(-2.2,3.43) 56(-2.6,3.43)
  rect 4.9x4.9 smd paste-4.9 mask+0: 57(0,0)
  Top region: -2.8,-2.8 -2.8,2.45 -2.45,2.8 2.8,2.8 2.8,-2.8 -2.8,-2.8
  body extent -3.55,-3.55 3.55,3.55, height 0.8
QFN50P320X250X90-15T140X210N [mm] "Quad Flat No-Lead (QFN with Tab), 0.50 mm pitch; rect., 4 pin X 3 pin, 3.20 mm L X 2.50 mm W X 0.90 mm H body"
  rrect25% 0.7x0.27 smd mask+0.05: 1(-1.25,0.75) 2(-1.25,0.25) 3(-1.25,-0.25) 4(-1.25,-0.75) 8(1.25,-0.75) 9(1.25,-0.25) 10(1.25,0.25) 11(1.25,0.75)
  rrect25% 0.27x0.7 smd mask+0.05: 5(-0.5,-1.6) 6(0,-1.6) 7(0.5,-1.6) 12(0.5,1.6) 13(0,1.6) 14(-0.5,1.6)
  rect 1.4x2.1 smd paste-2.1 mask+0: 15(0,0)
  body extent -1.3,-1.65 1.3,1.65, height 0.9
QFN50P600X600X100-37AN [mm]
  rrect50% 1.1x0.3 smd mask+0.05: 1(-2.8,2) 2(-2.8,1.5) 3(-2.8,1) 4(-2.8,0.5) 5(-2.8,0) 6(-2.8,-0.5) 7(-2.8,-1) 8(-2.8,-1.5) 9(-2.8,-2) 19(2.8,-2) 20(2.8,-1.5) 21(2.8,-1) 22(2.8,-0.5) 23(2.8,0) 24(2.8,0.5) 25(2.8,1) 26(2.8,1.5) 27(2.8,2)
  rrect50% 0.3x1.1 smd mask+0.05: 10(-2,-2.8) 11(-1.5,-2.8) 12(-1,-2.8) 13(-0.5,-2.8) 14(0,-2.8) 15(0.5,-2.8) 16(1,-2.8) 17(1.5,-2.8) 18(2,-2.8) 28(2,2.8) 29(1.5,2.8) 30(1,2.8) 31(0.5,2.8) 32(0,2.8) 33(-0.5,2.8) 34(-1,2.8) 35(-1.5,2.8) 36(-2,2.8)
  rect 3.8x3.8 smd: 37(0,0)
  body extent -3.05,-3.05 3.05,3.05, height 1.01
QFN_MPS_MP2316 [mm]
  rect 0.75x0.25 smd mask+0.05: 1(-0.8,1)
  rect 0.7x0.25 smd mask+0.05: 2(-0.8,0.5) 3(-0.8,0) 4(-0.8,-0.5) 5(-0.8,-1) 7(0.8,-1) 8(0.8,-0.5) 9(0.8,0) 10(0.8,0.5) 11(0.8,1)
  rect 0.25x0.7 smd mask+0.05: 6(0,-1.45) 12(0,1.45)
  rect 0.35x0.25 smd mask+0.05: 13(0,0.5) 14(0,0)
  body extent -1,-1.5 1,1.5, height 1.01
RESC1005X40N#1 [mm]
  rect 0.57x0.62 smd mask+0.05: 1(-0.48,0) 2(0.48,0)
  body extent -0.5,-0.25 0.5,0.25, height 0.4
RESC1005X40N#2 [mm]
  rrect25% 0.57x0.62 smd mask+0.05: 1(-0.48,0) 2(0.48,0)
  body extent -0.5,-0.25 0.5,0.25, height 0.4
RESC1609X55N [mm]
  rect 0.9x1 smd mask+0.05: 1(-0.8,0) 2(0.8,0)
  body extent -0.87,-0.48 0.87,0.48, height 0.55
RESC2013X70N [mm]
  rect 1.05x1.4 smd: 1(-0.95,0) 2(0.95,0)
  body extent -1.1,-0.67 1.1,0.68, height 0.7
RESC3225X60N [mm]
  rect 1.1x2.7 smd: 1(-1.5,0) 2(1.5,0)
  body extent -1.7,-1.35 1.7,1.35, height 0.6
SAMTEC_FTSH-105-01-F-DV [mil]
  rect 110x29 smd: 1(-80,100) 2(80,100) 3(-80,50) 4(80,50) 5(-80,0) 6(80,0) 7(-80,-50) 8(80,-50) 9(-80,-100) 10(80,-100)
  body extent -115,-208 115,208, height 325
SAMTEC_SMM-110-02-F-S [mm]
  rect 0.8x2.35 smd: 1(-9,-1.425) 2(-7,1.425) 3(-5,-1.425) 4(-3,1.425) 5(-1,-1.425) 6(1,1.425) 7(3,-1.425) 8(5,1.425) 9(7,-1.425) 10(9,1.425)
  body extent -10,-1 10,1, height 7.37
SOD3716X135N [mm]
  rect 1x0.8 smd: A(1.8,0) K(-1.8,0)
  body extent -1.85,-0.8 1.85,0.8, height 1.27
SODFL1006X43AN12 [mm]
  rect 0.43x0.32 smd: 1(-0.55,0) 2(0.55,0)
  body extent -0.58,-0.33 0.58,0.33, height 0.4
SODFL1006X43N12 [mm]
  rect 0.32x0.43 smd: 1(-0.55,0) 2(0.55,0)
  body extent -0.58,-0.33 0.58,0.33, height 0.4
SODFL2513X80N [mm]
  rrect25% 0.97x0.57 smd: A(1.07,0)
  rrect25% 0.97x0.6 smd: K(-1.07,0)
  body extent -1.25,-0.63 1.25,0.63, height 0.8
SOIC127P600X175-8N [mm]
  rect 1.97x0.6 smd mask+0.05: 1(-2.47,1.915) 2(-2.47,0.645) 3(-2.47,-0.625) 4(-2.47,-1.895) 5(2.47,-1.895) 6(2.47,-0.625) 7(2.47,0.645) 8(2.47,1.915)
  body extent -3.1,-2.48 3.1,2.52, height 1.75
SON50P120X160X60-5T55X91N [mm] "Small Outline No-Lead (SON with Tab), 0.50 mm pitch; 4 pin, 1.20 mm L X 1.60 mm W X 0.60 mm H body"
  rrect52% 0.67x0.27 smd mask+0.051: 1(-0.81,0.25) 2(-0.81,-0.25) 3(0.81,-0.25) 4(0.81,0.25)
  rect 0.55x0.91 smd paste-0.099 mask+0.025: 5(0,0)
  body extent -0.85,-0.6 0.85,0.6, height 0.6
SON50P250X100X50-10N [mm] "Small Outline No-Lead (SON), 0.50 mm pitch; 10 pin, 2.50 mm L X 1.00 mm W X 0.50 mm H body"
  rrect55% 0.7x0.22 smd mask+0.05: 1(-0.505,1) 2(-0.5,0.5) 3(-0.5,0) 4(-0.5,-0.5) 5(-0.5,-1) 6(0.5,-1) 7(0.5,-0.5) 8(0.5,0) 9(0.5,0.5) 10(0.5,1)
  body extent -0.55,-1.25 0.55,1.25, height 0.5
SON95P300X300X80-7N [mm]
  rect 0.4x1 smd: 1(-0.95,-1.4) 2(0,-1.4) 3(0.95,-1.4) 4(0.95,1.4) 5(0,1.4) 6(-0.95,1.4)
  rect 2x1.3 smd: 7(0,0)
  body extent -1.58,-1.58 1.58,1.58, height 0.8
SOT65P210X100-3AN [mm]
  rect 0.5x1 smd: 1(-0.65,-1.1) 2(0.65,-1.1) 3(0,1.1)
  body extent -1.2,-1.12 1.2,1.12, height 1
SOT65P210X110-6N [mm]
  rect 0.95x0.4 smd mask+0.05: 1(-1.1,0.65) 2(-1.1,0) 3(-1.1,-0.65) 4(1.1,-0.65) 5(1.1,0) 6(1.1,0.65)
  body extent -1.05,-1 1.05,1, height 1.1
SOT95P240X110-3N [mm]
  rrect50% 1.16x0.6 smd: 1(-1.03,0.95) 2(-1.03,-0.95) 3(1.03,0)
  body extent -1.2,-1.45 1.2,1.45, height 1.1
SOT95P240X110_GSD-3N [mm]
  rect 0.65x1.05 smd: D(0,1.15) G(-0.95,-1.15) S(0.95,-1.15)
  body extent -1.46,-1.2 1.46,1.2, height 1.1
SOT95P280X145-5N [mm]
  rrect50% 1.36x0.6 smd: 1(-1.18,0.95) 2(-1.18,0) 3(-1.18,-0.95) 4(1.18,-0.95) 5(1.18,0.95)
  body extent -1.4,-1.45 1.4,1.45, height 1.45
SOTFL50P160X60-6N [mm]
  rrect53% 0.56x0.3 smd mask+0.05: 1(-0.78,0.5) 2(-0.78,0) 3(-0.78,-0.5) 4(0.78,-0.5) 5(0.78,0) 6(0.78,0.5)
  body extent -0.8,-0.8 0.8,0.8, height 0.6
SOTFL50P160X80_GSD-3N [mm]
  rect 0.4x0.77 smd: D(0,0.69) G(-0.5,-0.69) S(0.5,-0.69)
  body extent -0.85,-0.85 0.85,0.85, height 0.8
SW_KSC221J [mm]
  rect 1x2.8 smd: 1(2,2.9) 2(2,-2.9) 3(-2,2.9) 4(-2,-2.9)
  body extent -3.1,-3.4 3.1,3.4, height 3.5
SW_TDA02 [mm]
  rect 1.27x0.76 smd: 1(-3.81,0.635) 2(-3.81,-0.635) 3(3.81,-0.635) 4(3.81,0.635)
  body extent -3.12,-1.84 3.13,1.84, height 2.3
TC_TC2050-IDC-NL#1 [mil]
  round 31 smd paste-50: 1(-100,-25) 2(-50,-25) 3(0,-25) 4(50,-25) 5(100,-25) 6(100,25) 7(50,25) 8(0,25) 9(-50,25) 10(-100,25)
  round 59 hole 39 unplated mask+0: MT1(-150,0) MT2(150,40) MT3(150,-40)
TC_TC2050-IDC-NL#2 [mil]
  round 31 smd paste-50: 1(-100,-25) 2(-50,-25) 3(0,-25) 4(50,-25) 5(100,-25) 6(100,25) 7(50,25) 8(0,25) 9(-50,25) 10(-100,25)
  round 0 hole 39 unplated mask+0: MT1(-150,0) MT2(150,40) MT3(150,-40)
TE_640456-2 [mm] "CONN HEADER VERT 2POS .100 TIN"
  round 1.5 hole 1.02: 1(-1.27,0) 2(1.27,0)
  body extent -2.54,-2.71 2.54,3.13, height 10.03
TP0762 [mil] "30mil SMT Round Testpoint"
  round 30 smd paste-100: 1(0,0)
XMULTIPLE_XMG-J1B211 [mil]
  rect 60x60 hole 35: 1(0,0)
  round 60 hole 35: 2(50,-100) 3(100,0) 4(150,-100) 5(200,0) 6(250,-100) 7(300,0) 8(350,-100) 9(400,0) 10(450,-100)
  round 76 hole 47.24: D1(-36.61,-510) D2(63.78,-510) D3(386.61,-510) D4(487.01,-510)
  round 127.95 hole 127.95 unplated: MNT1(0,-350) MNT2(450,-350)
  round 100 hole 63: SHLD1(-84.25,-230) SHLD2(534.25,-230)
  body extent -167,-773 620,67, height 612
XTAL_C3E-3427 [mm]
  rect 1.4x1.15 smd: 1(-1.1,-0.8) 2(1.1,-0.8) 3(1.1,0.8) 4(-1.1,0.8)
  body extent -1.7,-1.35 1.7,1.35, height 0.75

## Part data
C1 C7 C19 C20 C21 C155 C159: library part 1001196, "CAP TANT 100UF 6.3V 20% 1206", Manufacturer=Rohm, Manufacturer_Part_Number=TCTAL0J107M8R, Package_Type=3216, Tolerance=20%, Voltage=6.3V
C2 C6 C27 C47 C54 C65 C72 C85 C87 C90 C103 C104 C106 C120 C124 C149 C154 C158: library part 1001168, "CAP CER 10UF 10V 20% X5R 0402", Manufacturer=Samsung, Manufacturer_Part_Number=CL05A106MP5NUNC, Package_Type=0402, Temp_Coef=X5R, Tolerance=20%, Voltage=10V
C3 C50 C52 C53 C68 C70 C71 C83 C84 C121 C122 C123 C125 C126 C127 C128 C129 C131 C132 C147: library part 1001167, "CAP CER 1UF 10V 10% X5R 0402", Manufacturer=Murata, Manufacturer_Part_Number=GRM155R61A105KE15D, Package_Type=0402, Temp_Coef=X5R, Tolerance=10%, Voltage=10V
C4 C34 C35 C36 C79 C109 C110 C111: library part 1000073, "CAP CER 1UF 6.3V 20% X5R 0402", Manufacturer=Murata, Manufacturer_Part_Number=GRM155R60J105ME19D, Package_Type=0402, Temp_Coef=X5R, Voltage=6.3V
C5 C143: library part 1001303, "CAP CER 2.2UF 16V 10% X5R 0603", Manufacturer="TDK Corporation", Manufacturer_Part_Number=C1608X5R1C225K080AB, Package_Type=0603, Tolerance=10%, Voltage=16V
C8 C11 C156 C160: library part 1000998, "CAP CER 22UF 10V 20% X5R 0603", Manufacturer=Samsung, Manufacturer_Alt_1="TDK Corporation", Manufacturer_Alt_1_Part_Number=C1608X5R1A226M080AC, Manufacturer_Part_Number=CL10A226MP8NUNE, Package_Type=0603, Temp_Coef=X5R, Tolerance=20, Voltage=10V
C9 C13 C22 C23 C24 C25 C26 C28 C29 C30 C31 C32 C33 C38 C39 C40 C44 C45 C48 C49 C51 C55 C56 C57 C62 C63 C66 C67 C69 C73 C74 C75 C78 C80 C86 C88 C91 C92 C93 C94 C95 C96 C97 C98 C99 C100 C105 C107 C108 C139 C140 C145 C146 C148 C157 C161: library part 1000006, "CAP 100nF 16V 10% X7R 0402", Manufacturer=Murata, Manufacturer_Part_Number=GRM155R71C104KA88D, Package_Type=0402, Tolerance=10
C10: library part 1000501, "CAP CER 47UF 6.3V 20% X5R 0805", Manufacturer="Taiyo Yuden", Manufacturer_Part_Number=JMK212BJ476MG-T, Package_Type=0805, Temp_Coef=X5R, Tolerance=20%, Voltage=6.3V
C12 C46 C64 C118 C119 C150 C151 C152 C153: library part 1000918, "CAP CER 0.1UF 50V 10% X7R 0402", Manufacturer="TDK Corporation", Manufacturer_Part_Number=C1005X7R1H104K050BB, Package_Type=0402, Temp_Coef=X7R, Tolerance=10%, Voltage=50V
C14: library part 1000007, "CAP 47pF 50V 5% NP0 0402", Manufacturer=Murata, Manufacturer_Alt_1="AVX Corporation", Manufacturer_Alt_1_Part_Number=04025A470JAT2A, Manufacturer_Part_Number=GRM1555C1H470JA01D, Package_Type=0402, Temp_Coef="C0G, NP0"
C15 C16 C17 C18: library part 1000111, "CAP CER 10UF 16V 10% X5R 0805", Manufacturer=Murata, Manufacturer_Part_Number=GRM21BR61C106KE15L, Package_Type=0805, Temp_Coef=X5R, Tolerance=10, Voltage=16V
C37: library part 1000566, "CAP CER 100UF 10V 20% X5R 1206", Manufacturer="TDK Corporation", Manufacturer_Part_Number=C3216X5R1A107M, Package_Type=1206, Temp_Coef=X5R, Tolerance=20%, Voltage=10V
C41 C89 C133 C134: library part 1000067, "CAP CER 1000PF 50V 10% X7R 0402", Manufacturer=Murata, Manufacturer_Part_Number=GRM155R71H102KA01D, Package_Type=0402
C42 C43 C60 C61: library part 1001166, "CAP CER 22PF 50V 5% NP0 0402", Manufacturer=Murata, Manufacturer_Part_Number=GRM1555C1H220JA01D, Package_Type=0402, Temp_Coef="C0G, NP0", Tolerance=5%, Voltage=50V
C58 C59 C76 C77: library part 1001883, "CAP CER 0.22UF 6.3V X7R 0402", Manufacturer="Taiyo Yuden", Manufacturer_Part_Number=JMK105B7224KV-F, Package_Type=0402, Tolerance=10%, Voltage=6.3V
C81 C82: library part 1002646, "CAP CER 33PF 50V C0G/NP0 0402", Manufacturer=Murata, Manufacturer_Part_Number=GCM1555C1H330JA16D, Package_Type=0402, Tolerance=5%, Voltage=50
C101 C102 C130: library part 1000970, "CAP CER 2.2UF 6.3V 20% X5R 0402", Manufacturer="TDK Corporation", Manufacturer_Alt_1="Taiyo Yuden", Manufacturer_Alt_1_Part_Number=JMK105BJ225MV-F, Manufacturer_Part_Number=C1005X5R0J225M050BC, Package_Type=0402, Temp_Coef=X5R, Tolerance=20, Voltage=6.3V
C112 C113 C114 C115 C116 C117: library part 1001541, "CAP CER 10PF 50V 5% NP0 0402", Manufacturer=Murata, Manufacturer_Part_Number=GRM1555C1H100JA01D, Package_Type=0402, Temp_Coef="C0G, NP0", Tolerance=5, Voltage=50V
C135: library part 1000110, "CAP CER 1UF 25V 10% X5R 0603", Manufacturer=Murata, Manufacturer_Alt_1="AVX Corporation", Manufacturer_Alt_1_Part_Number=TMK107BJ105KA-T, Manufacturer_Part_Number=GRM188R61E105KA12D, Package_Type=0603, Temp_Coef=X5R, Tolerance=10%, Voltage=25V
C136 C142: library part 1000512, "CAP CER 0.015UF 16V 10% X7R 0402", Manufacturer=Murata, Manufacturer_Part_Number=GRM155R71C153KA01D, Package_Type=0402, Temp_Coef=X7R, Tolerance=10%, Voltage=16V
C137 C138: library part 1000963, "220nF, 10V, 20%, 0201", Manufacturer="TDK Corporation", Manufacturer_Alt_1="Taiyo Yuden", Manufacturer_Alt_1_Part_Number=LMK063BJ224MP-F, Manufacturer_Alt_2=AVX, Manufacturer_Alt_2_Part_Number=0201ZD224MAT2A, Manufacturer_Part_Number=C0603X5R1A224M030BB, Package_Type=0201, Temp_Coef=X5R, Tolerance=20%, Voltage=10V
C162: library part 1000463, "CAP CER 4.7UF 4V 20% X5R 0402", Manufacturer="Taiyo Yuden", Manufacturer_Part_Number=AMK105BJ475MV-F, Package_Type=0402, Temp_Coef=X5R, Tolerance=20%, Voltage=4V
CAD1 CAD2: library part CAD0066, "CBL PLUG-OF-NAILS 10-PIN", Package_Type=SMT
D1 D9 D10: library part 1002593, "TVS DIODE 5.5V 4V 10DFN", Manufacturer="Phillips NXP", Package_Type=SON
D2: library part 1001264, "TVS DIODE 5VWM SOD923", Manufacturer="On Semiconductor", Package_Type=SMT
D3: library part 1001494, "DIODE ZENER 5.1V 500MW SOD123", Manufacturer="On Semiconductor", Package_Type=SOD123
D4: library part 1000794, "DIODE SCHOTTKY 30V 200MA SOT323", Manufacturer="Fairchild Semiconductor", Manufacturer Alt 1=none, Manufacturer Part Num=0082610201, Package_Type=SOT323, Part Number=SDS1920004
D5 D11: library part 1001189, "LED GREEN 573NM 1208 SMD", Manufacturer=Dialight, Package_Type=SMT
D6 D7: library part 1001637, "TVS DIODE 3.3VWM SOD923", Manufacturer="On Semiconductor", Package_Type=SMT
D8: library part 1000231, "DIODE SCHOTTKY 40V 1A SOD123", Manufacturer="Diodes, Inc.", Package_Type=SOD123
D12: library part 1001188, "LED YELLOW 588NM 1208 SMD", Manufacturer=Dialight, Package_Type=SMT
D13: library part 1002592, "DIODE SCHOTTKY 30V 30MA SMINI2", Manufacturer="Panasonic - ECG", Package_Type=SODFL
D14: library part 1002782, "SMDIO,TVS UNI-DIR 5V 600W SMA", Manufacturer="Vishay Semiconductors", Manufacturer_Part_Number=SMA6J5.0A-M3/5A, Package_Type=SMA
FIDUCIAL1 FIDUCIAL2 FIDUCIAL3 FIDUCIAL4 FIDUCIAL5 FIDUCIAL6 FIDUCIAL7 FIDUCIAL8 FIDUCIAL9 FIDUCIAL10 FIDUCIAL11 FIDUCIAL12: library part CAD0023, "40 Mil Round Fiducial", Package_Type=SMT
FIL1: library part 1002768, "CAP FEEDTHRU 1UF 20% 10V 0805", Manufacturer=Murata, Package_Type=0805, Tolerance=±20%, Voltage=10
H1 H2 H3 H4: library part CAD0006, "NPTH for Tooling, 0.125in dia.", Package_Type=TH
J2 J3 J6: library part 1001136, "CONN HEADER 2POS 1.25MM VERT TIN", Manufacturer=Molex, Manufacturer_Part_Number=53047-0210, Package_Type=TH
J4: library part 1001105, "DC Power Jack", Manufacturer="Bobbintron Electrical Corp", Package_Type=TH
J5: library part 1002003, "CONN HEADER VERT 2POS .100 TIN", Manufacturer="TE Connectivity", Package_Type=TH
J7: library part 1001130, "SMCONN,MINI PCI EXP, 6.8MM HT", Manufacturer=Foxconn, Manufacturer_Part_Number=AS0B226-S68Q-7H, Package_Type=SMT
J8: library part 1001120, "MEMORY CARD 6POS PUSH/PULL SMD", Manufacturer=Molex, Package_Type=SMT
J9: library part 1000034, "CONN HEADER 10POS DUAL .05\" SMD", Manufacturer=Samtec, Package_Type=SMT
J10: library part 1001118, "CONN TRANSFLSH R/A PUSH-PUSH SMD", Manufacturer=Molex, Package_Type=SMT
J11: library part 1001137, "CONN HEADER 4POS 1.25MM VERT TIN", Manufacturer=Molex, Manufacturer_Part_Number=53047-0410, Package_Type=TH
J12 J13: library part 1002612, "CONN MAGJACK 1PORT 1000 BASE-T IND", Manufacturer=XMultiple, Manufacturer_Part_Number=XMG-J1B2211NPA-1-DIG, Package_Type=TH
J14 J16: library part 1001132, "CONN HEADER 20POS 1.25MM R/A SMD", Manufacturer=Hirose, Manufacturer_Part_Number=DF14A-20P-1.25H, Package_Type=SMT
J15: library part 1001866, "CONN FFC FPC VERT 15POS 1MM SMD", Manufacturer=FCI, Package_Type=SMT
J17: library part 1001145, "CONN FPC 20POS 0.5MM PITCH SMD", Manufacturer=Omron, Manufacturer_Part_Number=XF2M-2015-1A, Package_Type=SMT
J18: library part 1001121, "USB Stacked Dual A type", Manufacturer=KYCON, Package_Type=TH
J19: library part 1002675, "USB 3.1 SHIELDED I/O RECP TYPE C GEN2", Manufacturer=Molex, Manufacturer_Part_Number=201267-0005, Package_Type=SMT
J20 J27: library part 1002698, "CONN HEADER 40POS .100 PRESS-FIT", Manufacturer=Mill-Max, Manufacturer_Part_Number=802-10-040-62-001000, Package_Type=TH
J21: library part 1002596, "CONN JACK STEREO 3.5MM R/A", Manufacturer="CUI Inc.", Package_Type=TH
J22 J23: library part 1001495, "CONN RCPT 2MM 10POS SMD", Manufacturer=Samtec, Package_Type=SMT
J28: library part 1001117, "CONN RECEPT MICRO-USB TYPE AB R/A", Manufacturer=KYCON, Package_Type=SMT
L1: library part 1001912, "FIXED IND 1.5UH 4.5A 42 MOHM SMD", Manufacturer=Bourns, Manufacturer_Part_Number=SRP4020TA-1R5M, Package_Type=SMT, Tolerance=±20%
L2 L4 L5 L7: library part 1001175, "FERRITE BEAD 120 OHM .35A 0402", Manufacturer="Wurth Electronics Inc", Manufacturer_Part_Number=7427927112, Package_Type=0402
L3 L6: library part 1002610, "FIXED IND 4.7UH 1.1A 110 MOHM", Manufacturer=Samsung, Manufacturer_Part_Number=CIG22L4R7MNE, Package_Type=2520, Tolerance=20%
L8 L13 L14 L15 L22 L23 L29 L30 L36 L37 L39: library part 1001174, "FERRITE BEAD 220 OHM 2.0A 0805", Manufacturer="Wurth Electronics Inc", Manufacturer_Part_Number=742792022, Package_Type=0805
L9 L10 L11 L12 L38: library part 1001173, "CHOKE COM MODE 120 OHM .37A", Manufacturer="Wurth Electronics Inc", Package_Type=SMT
L16 L17 L18 L19 L20 L21: library part 1002041, "FERRITE BEAD 1.8 KOHM 0402 1LN", Manufacturer=Murata, Manufacturer_Part_Number=BLM15HD182SN1D, Package_Type=0402
L24 L25 L26 L27 L28 L31 L32 L33 L34 L35: library part 1001014, "CHOKE COIL COMMON MODE 150MA SMD", Manufacturer=Murata, Manufacturer_Part_Number=DLP11SN900HL2L, Package_Type=SMT
NT1: library part CAD0044, "NET TIE FOR I.MX6x SOM", Package_Type=NONE
Q1 Q2 Q3 Q4 Q5 Q8 Q13 Q14: library part 1000715, "MOSFET N-CH 60V 115MA SOT-523F", Manufacturer="Fairchild Semiconductor", Package_Type=SOT523F
Q6 Q9 Q10 Q11 Q12: library part 1000306, "MOSFET N-CH 30V 500MA SOT-23", Manufacturer="On Semiconductor", Package_Type=SOT23
Q7: library part 1001204, "TRANS GP SS PNP 40V SOT23", Manufacturer="On Semiconductor", Package_Type=SOT23
R1 R22 R31 R214 R255: library part 1001557, "RES 0.0 OHM 1/8W JUMP 0805 SMD", Manufacturer=Yageo, Manufacturer_Part_Number=RC0805JR-070RL, Package_Type=0805, Power=125
R2 R3 R4 R5 R6 R7 R8 R9 R11 R13 R14 R18 R28 R29 R34 R45 R56 R57 R65 R66 R67 R68 R76 R77 R78 R79 R155 R156 R157 R158 R164 R165 R173 R174 R175 R176 R177 R178 R185 R186 R187 R188 R189 R190 R191 R192 R196 R197 R205 R213 R221 R222 R223 R224 R225 R226 R227 R228 R229 R230 R231 R232 R233 R234 R238 R239 R240 R241 R242 R243 R245 R246 R247 R248 R249 R250 R252 R254 R256 R257: library part 1000076, "RES 0.0 OHM 1/10W 0402 SMD", Manufacturer="Panasonic - ECG", Manufacturer_Part_Number=ERJ-2GE0R00X, Package_Type=0402, Power=10
R10 R12 R16 R20 R21 R51 R52 R55 R70 R74 R75 R80 R86 R87 R88 R89 R90 R91 R92 R93 R94 R95 R96 R97 R98 R99 R100 R101 R106 R107 R118 R119 R120 R121 R122 R123 R124 R125 R126 R127 R128 R129 R130 R131 R132 R133 R134 R137 R142 R143 R145 R147 R148 R154 R163 R169 R193 R198 R215 R235 R244 R251 R253: library part 1000537, "RES 10.0K OHM 1/10W 1% 0402 SMD", Manufacturer="Panasonic - ECG", Manufacturer_Part_Number=ERJ-2RKF1002X, Package_Type=0402, Power=100, Tolerance=1%
R15: library part 1001313, "RES 51K OHM 1/10W 5% 0402 SMD", Manufacturer="Panasonic - ECG", Manufacturer_Part_Number=ERJ-2GEJ513X, Package_Type=0402, Power=100, Tolerance=5%
R17 R33 R37 R39 R40 R46 R47 R54 R69 R108 R109 R144 R153 R168 R194 R216 R259 R260: library part 1000480, "RES 100K OHM 1/10W 1% 0402 SMD", Manufacturer="Panasonic - ECG", Manufacturer_Part_Number=ERJ-2RKF1003X, Package_Type=0402, Power=100, Tolerance=1%
R19: library part 1001323, "RES 270 OHM 1/2W 5% 0805 SMD", Manufacturer="Panasonic - ECG", Manufacturer_Part_Number=ERJ-P06J271V, Package_Type=0805, Power=500, Tolerance=5%
R23 R59 R61 R72 R73 R104 R105 R151: library part 1000079, "RES 1.00K OHM 1/10W 1% 0402 SMD", Manufacturer="Panasonic - ECG", Manufacturer_Part_Number=ERJ-2RKF1001X, Package_Type=0402, Power=10
R24 R43 R44: library part 1000701, "RES 470K OHM 1/10W 1% 0402 SMD", Manufacturer="Panasonic - ECG", Manufacturer_Part_Number=ERJ-2RKF4703X, Package_Type=0402, Power=100, Tolerance=1%
R25: library part 1001917, "RES SMD 2.2M OHM 5% 1/10W 0402", Manufacturer="Panasonic - ECG", Manufacturer_Part_Number=ERJ-2GEJ225X, Package_Type=0402, Power=0,1
R26 R50 R102 R103: library part 1001200, "RES 12.0K OHM 1/10W 1% 0603 SMD", Manufacturer=Yageo, Manufacturer_Part_Number=RC0603FR-0712KL, Package_Type=0603, Power=100, Tolerance=1
R27: library part 1000142, "RES 20K OHM 1/10W 5% 0603 SMD", Manufacturer="Panasonic - ECG", Manufacturer_Part_Number=ERJ-3GEYJ203V, Package_Type=0603, Power=100, Tolerance=5
R30 R112 R117 R195 R217 R218: library part 1000466, "RES 49.9 OHM 1/10W 1% 0402 SMD", Manufacturer="Panasonic - ECG", Manufacturer_Part_Number=ERJ-2RKF49R9X, Package_Type=0402, Power=100, Tolerance=1%
R32 R35 R36 R38 R81 R113: library part 1000038, "RES 4.7K OHM 1/10W 5% 0402 SMD", Manufacturer="Panasonic - ECG", Manufacturer_Part_Number=ERJ-2GEJ472X, Package_Type=0402, Power=100, Tolerance=5
R41 R71 R146 R170 R199 R219 R220: library part 1000208, "RES 0.0 OHM 1/10W 0603", Manufacturer="Panasonic - ECG", Manufacturer_Part_Number=ERJ-3GEY0R00V, Package_Type=0603, Voltage=75V
R42: library part 1001154, "RES 220 OHM 1/16W 1% 0402 SMD", Manufacturer=Yageo, Manufacturer_Part_Number=RC0402FR-07220RL, Package_Type=0402, Tolerance=1%
R48: library part 1001916, "RES SMD 2 OHM 5% 1/10W 0603", Manufacturer="Panasonic - ECG", Manufacturer_Part_Number=ERJ-3GEYJ2R0V, Package_Type=0603, Power=100, Tolerance=1
R49: library part 1001518, "RES 53.6K OHM 1/10W 1% 0603 SMD", Manufacturer="Panasonic - ECG", Manufacturer_Part_Number=ERJ-3EKF5362V, Package_Type=0603
R53: library part 1001149, "RES 22.1K OHM 1/16W 1% 0402 SMD", Manufacturer="Vishay Dale", Manufacturer_Part_Number=CRCW040222K1FKED, Package_Type=0402, Power=0.063, Tolerance=±100ppm/°C
R58 R64 R160 R161 R166 R167: library part 1000467, "RES 100 OHM 1/10W 1% 0402 SMD", Manufacturer="Panasonic - ECG", Manufacturer_Part_Number=ERJ-2RKF1000X, Package_Type=0402, Tolerance=1%
R60 R62 R63 R203 R204: library part 1001158, "RES 120 OHM 1/16W 1% 0402 SMD", Manufacturer=Yageo, Manufacturer_Part_Number=RC0402FR-07120RL, Package_Type=0402, Tolerance=1%
R82 R114: library part 1000469, "RES 2.37K OHM 1/10W 1% 0402 SMD", Manufacturer="Panasonic - ECG", Manufacturer_Part_Number=ERJ-2RKF2371X, Package_Type=0402, Power=100, Tolerance=1%
R83 R84 R115 R116: library part 1000465, "RES 150 OHM 1/10W 1% 0402 SMD", Manufacturer="Panasonic - ECG", Manufacturer_Part_Number=ERJ-2RKF1500X, Package_Type=0402, Power=100, Tolerance=1%
R85: library part 1000229, "RES 0.0 OHM 1/2W 1210 SMD", Manufacturer="Vishay Dale", Manufacturer_Part_Number=CRCW12100000Z0EA, Package_Type=1210
R110 R111 R236 R237: library part 1000601, "RES 22.0 OHM 1/10W 1% 0402 SMD", Manufacturer="Panasonic - ECG", Manufacturer_Part_Number=ERJ-2RKF22R0X, Package_Type=0402, Power=100, Tolerance=1%
R135: library part 1000971, "RES 1.00M OHM 1/16W 1% 0402 SMD", Manufacturer=Yageo, Manufacturer_Part_Number=RC0402FR-071ML, Package_Type=0402, Power=63, Tolerance=1
R136 R138 R139 R140 R149 R258: library part 1001155, "RES 47.0K OHM 1/16W 1% 0402 SMD", Manufacturer="Vishay Dale", Manufacturer_Part_Number=CRCW040247K0FKED, Package_Type=0402, Tolerance=1%
R141: library part 1000828, "RES 12.1K OHM 1/10W 1% 0402 SMD", Manufacturer="Panasonic - ECG", Manufacturer_Part_Number=ERJ-2RKF1212X, Package_Type=0402, Power=100, Tolerance=1%
R150: library part 1000170, "RES 52.3K OHM 1/10W 1% 0402 SMD", Manufacturer="Panasonic - ECG", Manufacturer_Part_Number=ERJ-2RKF5232X, Package_Type=0402, Power=10, Tolerance=1%
R152: library part 1001149, "RES 22.1K OHM 1/16W 1% 0402 SMD", Manufacturer="Vishay Dale", Manufacturer_Part_Number=CRCW040222K1FKED, Package_Type=0402, Power=0,063, Tolerance=±100ppm/°C
R159 R171 R172 R179 R180 R181 R182 R183 R184: library part 1001156, "RES 2.20K OHM 1/16W 1% 0402 SMD", Manufacturer=Yageo, Manufacturer_Part_Number=RC0402FR-072K2L, Package_Type=0402, Tolerance=1%
R162: library part 1001917, "RES SMD 2.2M OHM 5% 1/10W 0402", Manufacturer="Panasonic - ECG", Manufacturer_Part_Number=ERJ-2GEJ225X, Package_Type=0402, Power=0.1
S2: library part 1001500, "SWITCH DIP 2POS HALF PITCH 24V", Manufacturer="C&K Components", Package_Type=SMT
SW1 SW2: library part 1001124, "SWITCH TACTILE SPST-NO 0.05A 32V", Manufacturer=ITT, Package_Type=SMT
TP1 TP2 TP3 TP4 TP5 TP6 TP7 TP8 TP9 TP10 TP13 TP14 TP15 TP16 TP18 TP19 TP20 TP21: library part CAD0011, "TEST POINT 30MIL PAD SMT", Package_Type=TP
U1: library part 1002581, "ConnectCore for i.MX8X module - LGA", Manufacturer=DIGI, Manufacturer_Part_Number=50001980-01, Package_Type=LGA
U2 U32 U33: library part 1001857, "IC SW W/CTRL SLEW RATE 4TDFN", Manufacturer="Vishay Siliconix", Manufacturer_Part_Number=SIP32401ADNP-T1GE4, Package_Type=SON
U3: library part 1001907, "IC REG BUCK ADJ 3A SYNC", Manufacturer="Linear Technology", Manufacturer_Part_Number=MP2316GD, Package_Type=QFN
U4 U5: library part 1001179, "IC SWITCH SPDT SC88", Manufacturer="On Semiconductor", Package_Type=SOT363
U6 U7: library part 1002681, "IC CAN TRANSEIVER HS 8SOIC", Manufacturer="Texas Instruments", Package_Type=SOIC
U8: library part 1001420, "IC TRANSCEIVER RS485 8-SOIC", Manufacturer="Linear Technology", Package_Type=SOIC
U9 U22: library part 1001009, "MOSFET DL N-CH 60V 410MA SOT-563", Manufacturer="Diodes, Inc.", Package_Type=SOT523F
U10: library part 1002531, "IC BUS TRANSCVR TRI-ST DL 10UQFN", Manufacturer="Texas Instruments", Manufacturer_Part_Number=SN74AVC2T245RSWR, Package_Type=QFN
U11 U12: library part 1002583, "IC TRANSCEIVER ETHERNET 48-QFN", Manufacturer="Qualcomm Atheros, Inc.", Package_Type=QFN
U13: library part 1001114, "4-PORT USB 2.0 HUB CTRLR 36VQFN", Manufacturer=SMSC, Package_Type=QFN
U14 U31: library part 1001143, "IC SW DISTRIBUTION 2CHAN 8SOIC", Manufacturer=Micrel, Manufacturer_Part_Number=MIC2026-1YM, Package_Type=SOIC
U15 U16: library part 1001265, "TVS DIODE 5.5VWM 6SON", Manufacturer="Texas Instruments", Package_Type=SMT
U17: library part 1002584, "IC DIFF SWITCH 2:1 HUQFN16", Manufacturer="NXP Semiconductors", Package_Type=QFN
U18: library part 1002585, "IC USB PD TCPC PHY HX2QFN16", Manufacturer="NXP Semiconductors", Package_Type=QFN
U19: library part 1002586, "IC USB POWER SWITCH 16WLCSP", Manufacturer="NXP Semiconductors", Package_Type=BGA
U20: library part 1002001, "IC CODEC AUDIO FLEXSOUND 56TQFN", Manufacturer=Maxim, Manufacturer_Part_Number=MAX98089ETN+T, Package_Type=QFN
U21 U23 U24 U25: library part 1001163, "MOSFET P-CH 20V 3.7A SOT23-3", Manufacturer="Vishay Siliconix", Package_Type=SMT
U26: library part 1001972, "MOSFET P-CH 12V 12A 6QFN", Manufacturer="Fairchild Semiconductors", Package_Type=DFN
U27: library part 1001979, "IC REG LDO ADJ 0.15A SOT25", Manufacturer="Diodes, Inc.", Manufacturer_Part_Number=AP2202K-ADJTRG1, Package_Type=SOT23-5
